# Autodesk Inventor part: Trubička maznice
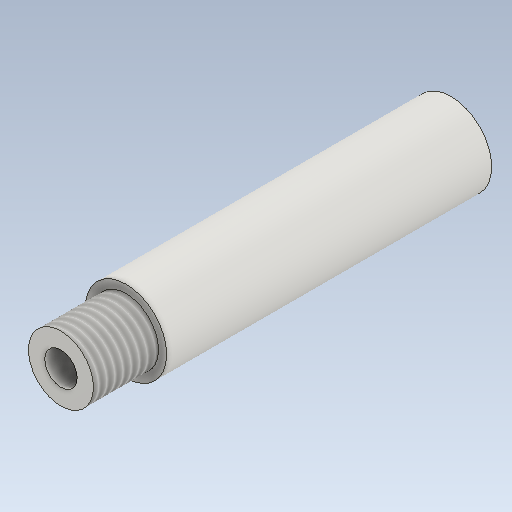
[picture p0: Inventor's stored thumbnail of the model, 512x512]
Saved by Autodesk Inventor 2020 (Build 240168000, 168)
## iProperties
Created: 2025-03
Part Number: Trubička maznice
Material: Ocel
Document SubType Name: Modeling
Designer: doma
Density: 7.85 g/cm^3
Appearance: Ocel
Mass: 21.0414 g
Surface Area: 22.7763 cm^2
Volume: 2.68044 cm^3
Author: doma
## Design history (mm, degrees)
sketch "Náčrt1"
  geometry: C1 r 5 at (0, 0); 1 further point
  constraints: 1 centre point, 1 coincident
  dimensions: "d0" = 10 diameter of C1
extrude "Vysunutí1" new body sketch "Náčrt1" distance "d1" = 40; taper "d2" = 0 deg
sketch "Náčrt2"
  geometry: C1 r 4 at (0, 0); 1 further point
  constraints: 1 centre point, 1 coincident
  dimensions: "d3" = 8 diameter of C1
extrude "Vysunutí2" join sketch "Náčrt2" distance "d4" = 8; taper "d5" = 0 deg
feature "Závit1" dims "d6" = 8, "d7" = 0
sketch "Náčrt4"
  geometry: C1 r 5 at (0, 0) reference; C2 r 2 at (0, 0); 2 further points
  constraints: 2 coincident, 1 centre point
  dimensions: "d15" = 4 diameter of C2
extrude "Vysunutí3" cut sketch "Náčrt4" extent not by distance; stored distance "d16" = 0; taper "d17" = 0 deg
hole "Díra2" sketch "Náčrt4" diameter "d18" = 6.917; stored, may be unused: countersink angle "d22" = 90 deg, drill point angle "d24" = 118 deg; dims "d19" = 6, "d20" = 4, "d21" = 2, "d23" = 10
node "Těleso1"
